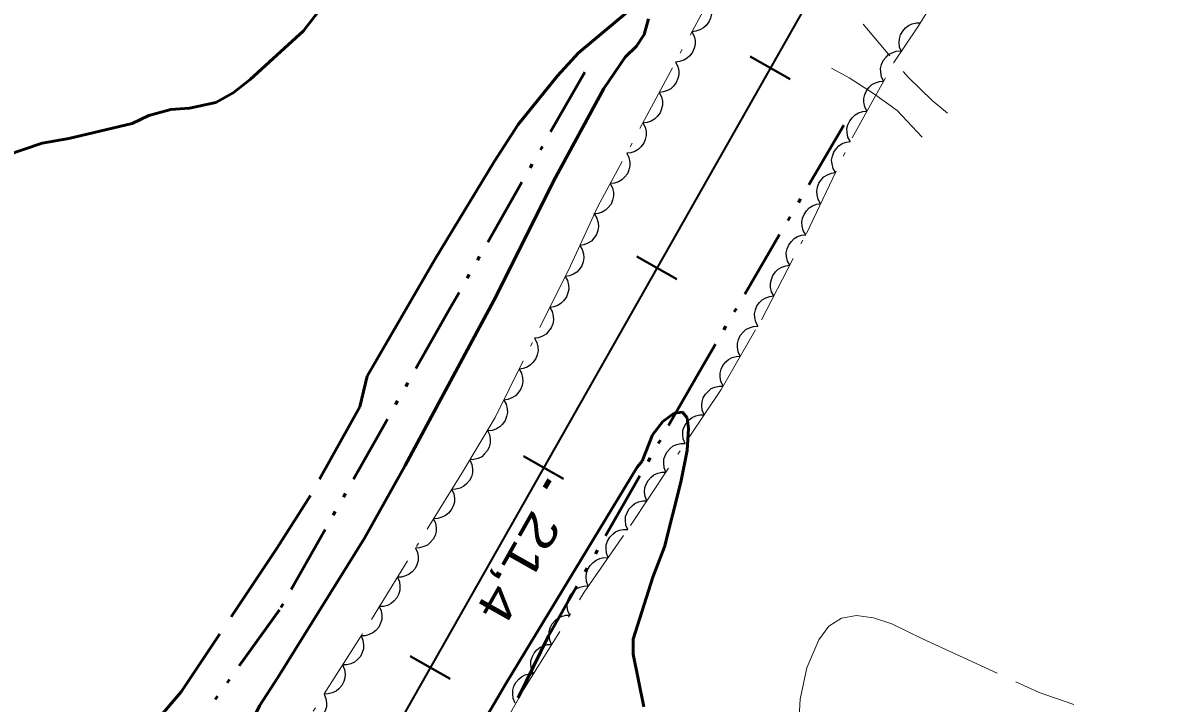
# Model space of a CAD drawing. Extents: x 386081 to 389416, y 5130568 to 5134082.
# Drawn here: x 387638.7 to 387738.2, y 5131704.1 to 5131763.3 of the extents above; entities that cross this region are included whole.
import ezdxf

# ---------------------------------------------------------------- set-up
doc = ezdxf.new("R2010")
doc.units = 0
doc.header["$LTSCALE"] = 1.2
for name, pattern in [('DASH_DOUBLE_DOT', [9.2, 5, -1.2, 0.3, -1.2, 0.3, -1.2]), ('DOT_DASHED', [7.7, 5, -1.2, 0.3, -1.2]), ('LONG_DASHED', [7.5, 6, -1.5]), ('MEDIUM_DASHED', [4.5, 3, -1.5])]:
    doc.linetypes.add(name, pattern=pattern)
for name, color, linetype, lineweight in [('1', 7, 'Continuous', 53), ('19', 7, 'Continuous', 13), ('2', 7, 'Continuous', 13), ('23', 7, 'Continuous', 40), ('3', 7, 'Continuous', 140), ('4', 7, 'DASH_DOUBLE_DOT', 53), ('44', 7, 'Continuous', 25)]:
    doc.layers.add(name, color=color, linetype=linetype, lineweight=lineweight)

msp = doc.modelspace()

# ---------------------------------------------------------------- linework, layer by layer
at = {"layer": '1', "linetype": 'LONG_DASHED'}
for points in [[(387637.19, 5131751.76), (387640.34, 5131752.84), (387642.65, 5131753.24), (387648.18, 5131754.55), (387649.61, 5131755.25), (387651.54, 5131755.79), (387653.16, 5131755.9), (387655.45, 5131756.38), (387656.95, 5131757.22), (387658.43, 5131758.4), (387663.09, 5131762.62), (387664.37, 5131764.28)], [(387668.62, 5131732.58), (387667.98, 5131729.91), (387663.69, 5131722.18), (387660.79, 5131717.62), (387652.43, 5131705.09), (387650.44, 5131702.73), (387648.24, 5131700.63), (387646.59, 5131699.55), (387644.58, 5131697.83), (387642.57, 5131696.67), (387641.46, 5131696.42), (387639.73, 5131696.41), (387638.42, 5131696.75)], [(387692.55, 5131725.18), (387693.46, 5131727.46), (387694.35, 5131728.61), (387695.35, 5131729.34), (387696.07, 5131729.42), (387696.46, 5131728.95), (387696.6, 5131728), (387696.48, 5131726.11), (387695.93, 5131723.34), (387694.5, 5131717.7), (387693.5, 5131715.07), (387691.78, 5131709.68), (387691.78, 5131708.38), (387692.7, 5131703.8)]]:
    msp.add_lwpolyline(points, dxfattribs=at)
at = {"layer": '1'}
for points in [[(387638.53, 5131662.5), (387640.21, 5131665.69), (387643.47, 5131671.05), (387645.1, 5131673.09), (387647.28, 5131676.45), (387648.48, 5131678.88), (387650.64, 5131682.51), (387655.26, 5131690.95), (387656.95, 5131694.8), (387657.66, 5131697.32), (387658.2, 5131701.69), (387659.26, 5131703.87), (387660.86, 5131706.33), (387668.38, 5131718.48), (387671.94, 5131724.8), (387679.85, 5131739.53), (387684.83, 5131749.55), (387689.23, 5131757.59), (387691.08, 5131760.34), (387692.07, 5131761.28), (387692.72, 5131762.3), (387693.12, 5131763.66)], [(387691.25, 5131764.24), (387687.01, 5131760.72), (387685.19, 5131758.72), (387681.77, 5131754.46), (387679.71, 5131751.29), (387674.5, 5131742.72), (387668.62, 5131732.58)], [(387644.61, 5131638.59), (387647.88, 5131646.7), (387650.51, 5131652.41), (387651.89, 5131654.59), (387658.42, 5131665.69), (387665.52, 5131678.48), (387666.82, 5131681.51), (387669.58, 5131687.03), (387671.63, 5131690.38), (387680.71, 5131705.84), (387692.13, 5131724.66), (387692.55, 5131725.18)]]:
    msp.add_lwpolyline(points, dxfattribs=at)
at = {"layer": '19', "linetype": 'MEDIUM_DASHED'}
for points in [[(387711.79, 5131763.2), (387715.71, 5131758.58), (387717.81, 5131756.55), (387719.14, 5131755.45)], [(387716.94, 5131753.36), (387714.75, 5131755.7), (387712.7, 5131757.17), (387710.56, 5131758.53), (387709.04, 5131759.38)]]:
    msp.add_lwpolyline(points, dxfattribs=at)
at = {"layer": '2', "linetype": 'LONG_DASHED'}
msp.add_lwpolyline([(387706.1, 5131700.73), (387706.31, 5131704.45), (387706.88, 5131707.19), (387707.92, 5131709.63), (387708.79, 5131710.82), (387709.9, 5131711.51), (387711.21, 5131711.73), (387712.7, 5131711.54), (387714.29, 5131711.01), (387716.91, 5131709.73), (387727.11, 5131705.03), (387730.12, 5131704)], dxfattribs=at)
at = {"layer": '23'}
for p, q in [((387701.96, 5131760.38), (387705.44, 5131758.41)), ((387692.09, 5131742.99), (387695.57, 5131741.01)), ((387682.22, 5131725.59), (387685.7, 5131723.62)), ((387672.36, 5131708.19), (387675.84, 5131706.22))]:
    msp.add_line(p, q, dxfattribs=at)
at = {"layer": '23', "lineweight": 35}
msp.add_lwpolyline([(388350.66, 5132898.63), (388202.91, 5132638.38), (388174.85, 5132589.18), (388148.16, 5132542.09), (388122.46, 5132497.01), (388036.96, 5132346.4), (388027.91, 5132330.61), (387994.29, 5132271.3), (387943.96, 5132182.8), (387915.65, 5132132.74), (387888.36, 5132084.71), (387863.09, 5132039.98), (387797.42, 5131924.62), (387647.54, 5131660.34), (387567.35, 5131519.3), (387534.84, 5131461.86), (387476.24, 5131358.73)], dxfattribs=at)
at = {"layer": '3'}
msp.add_line((387684.48, 5131723.55), (387684.09, 5131722.85), dxfattribs=at)
at = {"layer": '4'}
for points in [[(387687.56, 5131759.03), (387675.82, 5131738.45), (387661, 5131712.22), (387651.45, 5131698.94), (387643.62, 5131688.48), (387639.31, 5131683.05), (387635.14, 5131678.96)], [(387710.1, 5131754.41), (387697.83, 5131733.47), (387684.4, 5131709.96), (387677.42, 5131695.63), (387674.76, 5131687.46), (387671.55, 5131676.22), (387670.04, 5131669.72), (387667.22, 5131660.49)]]:
    msp.add_lwpolyline(points, dxfattribs=at)
at = {"layer": '44', "linetype": 'DOT_DASHED', "lineweight": 13}
for points in [[(387629.7, 5131608.49), (387640.15, 5131626.74), (387643.25, 5131632.84), (387655.58, 5131656.43), (387657.97, 5131660.13), (387668.5, 5131677.07), (387679.89, 5131701.17), (387682.22, 5131705.26), (387687.51, 5131713.78), (387691.54, 5131719.57), (387699.42, 5131731.42), (387702.94, 5131737.48), (387706.85, 5131744.99), (387710.82, 5131753.3), (387714.47, 5131759.86), (387716.56, 5131762.97), (387721.58, 5131771.05)], [(387699.57, 5131767.54), (387688.71, 5131747.33), (387686.31, 5131742.17), (387679.76, 5131728.98), (387677.01, 5131724.36), (387668.11, 5131709.98), (387653.22, 5131686.59), (387643.37, 5131670.54), (387639.04, 5131662.83), (387616.76, 5131623.8)]]:
    msp.add_lwpolyline(points, dxfattribs=at)
at = {"layer": '44'}
for points in [[(387698.31, 5131765.19), (387698.5, 5131764.82), (387698.58, 5131764.42), (387698.59, 5131764.09), (387698.51, 5131763.74), (387698.37, 5131763.41), (387698.13, 5131763.1), (387697.9, 5131762.87), (387697.59, 5131762.7), (387697.24, 5131762.58), (387696.89, 5131762.54)], [(387696.89, 5131762.54), (387697.08, 5131762.17), (387697.16, 5131761.77), (387697.17, 5131761.44), (387697.09, 5131761.1), (387696.95, 5131760.76), (387696.71, 5131760.46), (387696.48, 5131760.23), (387696.17, 5131760.06), (387695.82, 5131759.94), (387695.47, 5131759.9)], [(387715.12, 5131760.82), (387714.96, 5131761.21), (387714.92, 5131761.61), (387714.94, 5131761.94), (387715.05, 5131762.28), (387715.23, 5131762.6), (387715.49, 5131762.88), (387715.74, 5131763.09), (387716.07, 5131763.22), (387716.43, 5131763.31), (387716.79, 5131763.31)], [(387713.57, 5131758.25), (387713.39, 5131758.62), (387713.32, 5131759.02), (387713.3, 5131759.35), (387713.39, 5131759.69), (387713.54, 5131760.03), (387713.78, 5131760.33), (387714.01, 5131760.56), (387714.32, 5131760.72), (387714.67, 5131760.84), (387715.03, 5131760.87)], [(387695.47, 5131759.9), (387695.66, 5131759.53), (387695.74, 5131759.13), (387695.75, 5131758.8), (387695.67, 5131758.46), (387695.53, 5131758.12), (387695.29, 5131757.82), (387695.06, 5131757.58), (387694.75, 5131757.42), (387694.4, 5131757.3), (387694.05, 5131757.26)], [(387712.12, 5131755.63), (387711.93, 5131756), (387711.86, 5131756.4), (387711.84, 5131756.73), (387711.93, 5131757.07), (387712.08, 5131757.41), (387712.32, 5131757.71), (387712.55, 5131757.94), (387712.86, 5131758.1), (387713.22, 5131758.22), (387713.57, 5131758.25)], [(387694.05, 5131757.26), (387694.24, 5131756.89), (387694.32, 5131756.49), (387694.33, 5131756.16), (387694.25, 5131755.82), (387694.11, 5131755.48), (387693.87, 5131755.18), (387693.64, 5131754.94), (387693.33, 5131754.77), (387692.98, 5131754.65), (387692.63, 5131754.62)], [(387710.66, 5131753.01), (387710.47, 5131753.38), (387710.4, 5131753.78), (387710.38, 5131754.11), (387710.47, 5131754.45), (387710.62, 5131754.79), (387710.86, 5131755.09), (387711.09, 5131755.32), (387711.4, 5131755.48), (387711.76, 5131755.6), (387712.12, 5131755.63)], [(387692.63, 5131754.62), (387692.82, 5131754.25), (387692.9, 5131753.85), (387692.91, 5131753.52), (387692.83, 5131753.17), (387692.69, 5131752.84), (387692.45, 5131752.53), (387692.22, 5131752.3), (387691.91, 5131752.13), (387691.56, 5131752.01), (387691.21, 5131751.97)], [(387709.38, 5131750.29), (387709.17, 5131750.65), (387709.08, 5131751.05), (387709.04, 5131751.37), (387709.11, 5131751.72), (387709.24, 5131752.07), (387709.46, 5131752.38), (387709.67, 5131752.62), (387709.97, 5131752.81), (387710.32, 5131752.94), (387710.68, 5131753)], [(387691.21, 5131751.97), (387691.4, 5131751.6), (387691.47, 5131751.2), (387691.49, 5131750.87), (387691.41, 5131750.53), (387691.27, 5131750.19), (387691.03, 5131749.89), (387690.8, 5131749.65), (387690.49, 5131749.49), (387690.14, 5131749.37), (387689.78, 5131749.33)], [(387708.09, 5131747.58), (387707.88, 5131747.94), (387707.78, 5131748.34), (387707.75, 5131748.67), (387707.81, 5131749.01), (387707.94, 5131749.36), (387708.16, 5131749.67), (387708.38, 5131749.92), (387708.68, 5131750.1), (387709.03, 5131750.24), (387709.38, 5131750.29)], [(387689.78, 5131749.33), (387689.98, 5131748.96), (387690.05, 5131748.56), (387690.07, 5131748.23), (387689.99, 5131747.89), (387689.85, 5131747.55), (387689.61, 5131747.25), (387689.38, 5131747.01), (387689.07, 5131746.85), (387688.72, 5131746.72), (387688.36, 5131746.69)], [(387706.8, 5131744.88), (387706.58, 5131745.24), (387706.49, 5131745.63), (387706.46, 5131745.96), (387706.52, 5131746.31), (387706.65, 5131746.65), (387706.87, 5131746.97), (387707.09, 5131747.21), (387707.39, 5131747.39), (387707.73, 5131747.53), (387708.09, 5131747.58)], [(387688.4, 5131746.67), (387688.62, 5131746.31), (387688.72, 5131745.92), (387688.75, 5131745.59), (387688.69, 5131745.24), (387688.57, 5131744.89), (387688.35, 5131744.58), (387688.14, 5131744.33), (387687.84, 5131744.15), (387687.49, 5131744.01), (387687.14, 5131743.95)], [(387705.41, 5131742.22), (387705.21, 5131742.58), (387705.13, 5131742.98), (387705.1, 5131743.31), (387705.18, 5131743.66), (387705.32, 5131744), (387705.55, 5131744.3), (387705.78, 5131744.54), (387706.09, 5131744.71), (387706.43, 5131744.84), (387706.79, 5131744.88)], [(387687.14, 5131743.95), (387687.35, 5131743.59), (387687.45, 5131743.2), (387687.49, 5131742.87), (387687.43, 5131742.52), (387687.3, 5131742.17), (387687.08, 5131741.86), (387686.87, 5131741.61), (387686.57, 5131741.43), (387686.23, 5131741.29), (387685.87, 5131741.23)], [(387704.02, 5131739.56), (387703.82, 5131739.92), (387703.74, 5131740.32), (387703.72, 5131740.65), (387703.8, 5131740.99), (387703.94, 5131741.34), (387704.17, 5131741.64), (387704.39, 5131741.88), (387704.7, 5131742.05), (387705.05, 5131742.18), (387705.41, 5131742.22)], [(387685.85, 5131741.24), (387686.05, 5131740.88), (387686.14, 5131740.48), (387686.17, 5131740.15), (387686.1, 5131739.81), (387685.97, 5131739.46), (387685.74, 5131739.15), (387685.52, 5131738.91), (387685.22, 5131738.73), (387684.87, 5131738.6), (387684.51, 5131738.55)], [(387702.64, 5131736.9), (387702.44, 5131737.26), (387702.36, 5131737.66), (387702.33, 5131737.99), (387702.41, 5131738.33), (387702.55, 5131738.68), (387702.78, 5131738.98), (387703.01, 5131739.22), (387703.31, 5131739.39), (387703.66, 5131739.51), (387704.02, 5131739.56)], [(387684.51, 5131738.55), (387684.72, 5131738.19), (387684.81, 5131737.79), (387684.84, 5131737.46), (387684.77, 5131737.12), (387684.63, 5131736.78), (387684.41, 5131736.47), (387684.19, 5131736.22), (387683.88, 5131736.05), (387683.54, 5131735.91), (387683.18, 5131735.87)], [(387701.1, 5131734.32), (387700.92, 5131734.69), (387700.86, 5131735.09), (387700.85, 5131735.42), (387700.94, 5131735.76), (387701.1, 5131736.1), (387701.35, 5131736.39), (387701.58, 5131736.62), (387701.9, 5131736.78), (387702.25, 5131736.89), (387702.61, 5131736.91)], [(387683.18, 5131735.87), (387683.39, 5131735.5), (387683.47, 5131735.11), (387683.5, 5131734.78), (387683.43, 5131734.43), (387683.3, 5131734.09), (387683.07, 5131733.78), (387682.85, 5131733.54), (387682.55, 5131733.36), (387682.2, 5131733.23), (387681.85, 5131733.18)], [(387699.6, 5131731.72), (387699.41, 5131732.1), (387699.35, 5131732.5), (387699.34, 5131732.83), (387699.44, 5131733.17), (387699.59, 5131733.5), (387699.84, 5131733.8), (387700.07, 5131734.03), (387700.39, 5131734.18), (387700.74, 5131734.29), (387701.1, 5131734.32)], [(387681.85, 5131733.18), (387682.05, 5131732.82), (387682.14, 5131732.42), (387682.17, 5131732.09), (387682.1, 5131731.75), (387681.96, 5131731.4), (387681.74, 5131731.09), (387681.52, 5131730.85), (387681.21, 5131730.67), (387680.87, 5131730.54), (387680.51, 5131730.49)], [(387697.95, 5131729.21), (387697.79, 5131729.6), (387697.76, 5131730), (387697.77, 5131730.33), (387697.88, 5131730.67), (387698.06, 5131730.99), (387698.32, 5131731.27), (387698.57, 5131731.48), (387698.89, 5131731.62), (387699.25, 5131731.71), (387699.61, 5131731.71)], [(387680.51, 5131730.49), (387680.72, 5131730.13), (387680.81, 5131729.73), (387680.83, 5131729.4), (387680.76, 5131729.06), (387680.63, 5131728.71), (387680.4, 5131728.4), (387680.18, 5131728.16), (387679.88, 5131727.99), (387679.53, 5131727.85), (387679.18, 5131727.81)], [(387696.29, 5131726.71), (387696.13, 5131727.1), (387696.09, 5131727.51), (387696.11, 5131727.84), (387696.22, 5131728.17), (387696.4, 5131728.49), (387696.66, 5131728.77), (387696.91, 5131728.98), (387697.23, 5131729.12), (387697.59, 5131729.21), (387697.95, 5131729.21)], [(387679.09, 5131727.85), (387679.27, 5131727.48), (387679.33, 5131727.07), (387679.33, 5131726.74), (387679.23, 5131726.4), (387679.07, 5131726.07), (387678.82, 5131725.78), (387678.59, 5131725.55), (387678.27, 5131725.4), (387677.91, 5131725.3), (387677.55, 5131725.28)], [(387694.63, 5131724.22), (387694.47, 5131724.6), (387694.43, 5131725.01), (387694.45, 5131725.34), (387694.56, 5131725.67), (387694.74, 5131725.99), (387695, 5131726.27), (387695.25, 5131726.49), (387695.57, 5131726.62), (387695.93, 5131726.71), (387696.29, 5131726.71)], [(387677.57, 5131725.27), (387677.74, 5131724.88), (387677.79, 5131724.48), (387677.79, 5131724.15), (387677.69, 5131723.81), (387677.52, 5131723.48), (387677.27, 5131723.2), (387677.03, 5131722.98), (387676.71, 5131722.83), (387676.35, 5131722.73), (387675.99, 5131722.71)], [(387692.97, 5131721.72), (387692.81, 5131722.1), (387692.77, 5131722.51), (387692.78, 5131722.84), (387692.9, 5131723.17), (387693.08, 5131723.5), (387693.34, 5131723.78), (387693.58, 5131723.99), (387693.91, 5131724.13), (387694.27, 5131724.21), (387694.63, 5131724.22)], [(387675.99, 5131722.71), (387676.16, 5131722.33), (387676.21, 5131721.93), (387676.21, 5131721.6), (387676.11, 5131721.26), (387675.94, 5131720.93), (387675.69, 5131720.65), (387675.45, 5131720.43), (387675.13, 5131720.28), (387674.77, 5131720.18), (387674.41, 5131720.16)], [(387691.31, 5131719.22), (387691.15, 5131719.61), (387691.11, 5131720.01), (387691.12, 5131720.34), (387691.24, 5131720.67), (387691.41, 5131721), (387691.68, 5131721.28), (387691.92, 5131721.49), (387692.25, 5131721.63), (387692.61, 5131721.72), (387692.97, 5131721.72)], [(387674.41, 5131720.16), (387674.58, 5131719.78), (387674.64, 5131719.38), (387674.63, 5131719.05), (387674.53, 5131718.71), (387674.36, 5131718.38), (387674.11, 5131718.1), (387673.87, 5131717.87), (387673.55, 5131717.73), (387673.19, 5131717.63), (387672.83, 5131717.61)], [(387689.59, 5131716.76), (387689.44, 5131717.15), (387689.41, 5131717.56), (387689.43, 5131717.89), (387689.55, 5131718.22), (387689.73, 5131718.54), (387690, 5131718.81), (387690.25, 5131719.02), (387690.58, 5131719.15), (387690.94, 5131719.23), (387691.3, 5131719.23)], [(387672.83, 5131717.61), (387673.01, 5131717.23), (387673.06, 5131716.83), (387673.05, 5131716.5), (387672.95, 5131716.16), (387672.79, 5131715.83), (387672.53, 5131715.54), (387672.29, 5131715.32), (387671.97, 5131715.18), (387671.61, 5131715.08), (387671.26, 5131715.06)], [(387687.87, 5131714.3), (387687.72, 5131714.69), (387687.69, 5131715.1), (387687.71, 5131715.43), (387687.83, 5131715.76), (387688.02, 5131716.08), (387688.29, 5131716.35), (387688.54, 5131716.56), (387688.86, 5131716.69), (387689.23, 5131716.77), (387689.59, 5131716.76)], [(387671.26, 5131715.06), (387671.43, 5131714.68), (387671.48, 5131714.28), (387671.48, 5131713.95), (387671.37, 5131713.61), (387671.21, 5131713.28), (387670.95, 5131712.99), (387670.71, 5131712.77), (387670.39, 5131712.62), (387670.04, 5131712.53), (387669.68, 5131712.51)], [(387686.26, 5131711.77), (387686.09, 5131712.15), (387686.04, 5131712.55), (387686.04, 5131712.89), (387686.15, 5131713.22), (387686.31, 5131713.55), (387686.57, 5131713.84), (387686.81, 5131714.06), (387687.13, 5131714.21), (387687.48, 5131714.3), (387687.84, 5131714.32)], [(387669.68, 5131712.51), (387669.85, 5131712.13), (387669.9, 5131711.73), (387669.9, 5131711.4), (387669.79, 5131711.06), (387669.63, 5131710.73), (387669.37, 5131710.44), (387669.13, 5131710.22), (387668.81, 5131710.07), (387668.46, 5131709.97), (387668.1, 5131709.96)], [(387684.68, 5131709.22), (387684.51, 5131709.6), (387684.46, 5131710.01), (387684.46, 5131710.34), (387684.56, 5131710.67), (387684.73, 5131711), (387684.98, 5131711.29), (387685.22, 5131711.51), (387685.54, 5131711.66), (387685.9, 5131711.76), (387686.26, 5131711.77)], [(387668.1, 5131709.96), (387668.26, 5131709.58), (387668.31, 5131709.17), (387668.3, 5131708.84), (387668.2, 5131708.51), (387668.03, 5131708.18), (387667.77, 5131707.9), (387667.53, 5131707.68), (387667.2, 5131707.53), (387666.85, 5131707.44), (387666.49, 5131707.43)], [(387683.1, 5131706.67), (387682.93, 5131707.05), (387682.88, 5131707.46), (387682.88, 5131707.79), (387682.98, 5131708.12), (387683.15, 5131708.45), (387683.4, 5131708.74), (387683.64, 5131708.96), (387683.96, 5131709.11), (387684.32, 5131709.21), (387684.68, 5131709.22)], [(387666.49, 5131707.43), (387666.65, 5131707.05), (387666.7, 5131706.64), (387666.69, 5131706.31), (387666.59, 5131705.98), (387666.42, 5131705.65), (387666.16, 5131705.36), (387665.92, 5131705.15), (387665.59, 5131705), (387665.24, 5131704.91), (387664.88, 5131704.9)], [(387681.51, 5131704.12), (387681.34, 5131704.51), (387681.29, 5131704.91), (387681.3, 5131705.24), (387681.4, 5131705.58), (387681.57, 5131705.91), (387681.82, 5131706.19), (387682.06, 5131706.41), (387682.38, 5131706.56), (387682.74, 5131706.66), (387683.1, 5131706.67)], [(387664.88, 5131704.9), (387665.04, 5131704.52), (387665.09, 5131704.11), (387665.08, 5131703.78), (387664.97, 5131703.45), (387664.8, 5131703.12), (387664.55, 5131702.83), (387664.3, 5131702.62), (387663.98, 5131702.47), (387663.62, 5131702.38), (387663.26, 5131702.37)]]:
    msp.add_lwpolyline(points, dxfattribs=at)

# ---------------------------------------------------------------- texts
at = {"layer": '3', "width": 1.3}
msp.add_text('21,4   ', height=3, rotation=240.518, dxfattribs=at).set_placement((387683.03, 5131721.06))

doc.saveas('drawing.dxf')
